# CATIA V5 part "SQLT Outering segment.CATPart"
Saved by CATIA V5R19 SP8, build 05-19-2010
Part number: SQLT Outering Segment 6a
Publications: "Droite.1", "Plan.1", "Plan.2", "Droite.2", "Droite.3", "Point.3"
Bounding box of the stored display mesh (mm): x -150 to 150, y 450 to 600, z 600 to 900
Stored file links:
  G:\EU_thinkMotion\CFAO_2010\MMS_groupe3\MMS_groupe3\A reprendre\fovide\fovide\SQLT Outering segment.CATPart
  G:\EU_thinkMotion\CFAO_2010\MMS_groupe3\MMS_groupe3\A reprendre\fovide\fovide\fovide.CATProduct
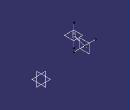
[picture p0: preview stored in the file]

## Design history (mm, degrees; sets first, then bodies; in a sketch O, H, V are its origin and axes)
Set1
  Point1 "Point.B": linked copy from another document
  Point2 "Point.C": linked copy from another document
Set2 "set Outering Segment"
  Line1: type PtPt, FirstPoint Point1, SecondPoint Point2
  Plane1: type OffsetPt, RefPlane xy-plane, RefPoint Point1
  Plane2: type OffsetPt, RefPlane yz-plane, RefPoint Point2
  Line2: type Normal, RefPoint Point1, RefSkin Plane1, Start -150, End 150
  Line3: type Normal, RefPoint Point2, RefSkin Plane2, Start -150, End 150
  Point3: type OnCurve, Support Line2, Length 130
Body1 (main body)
